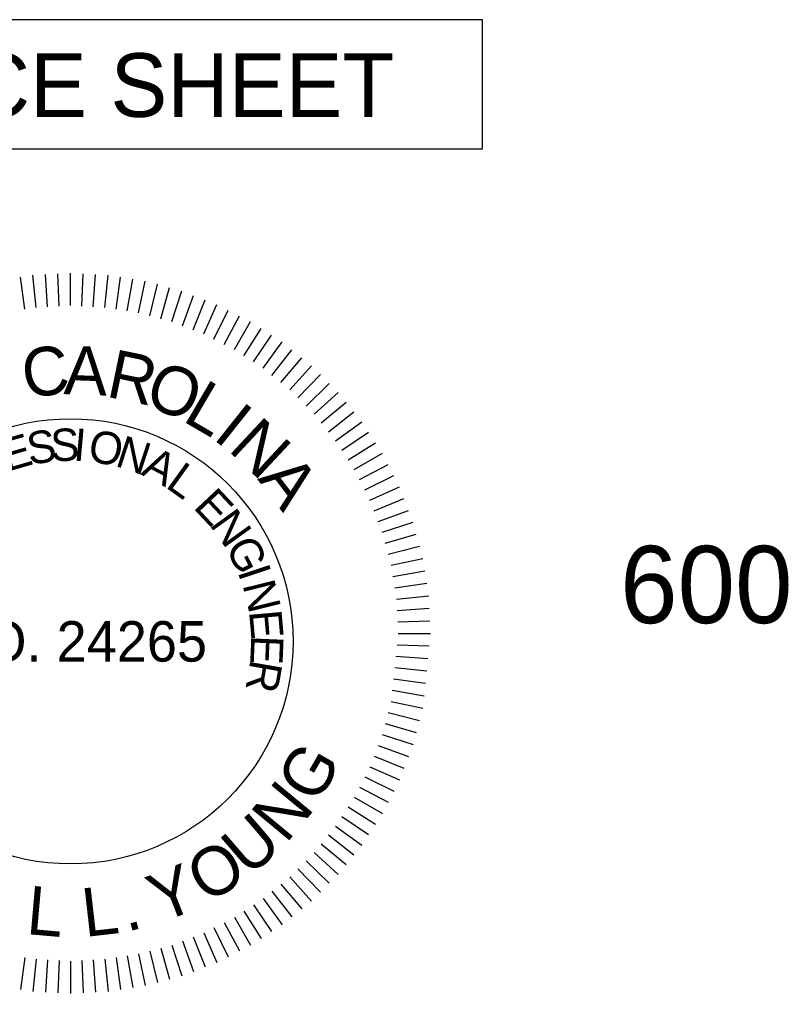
# Model space of a CAD drawing. Extents: x 1964377 to 1966966, y 1116414 to 1123213.
# Drawn here: x 1966865.3 to 1966949.9, y 1120286.1 to 1120393.2 of the extents above; entities that cross this region are included whole.
import ezdxf

# ---------------------------------------------------------------- set-up
doc = ezdxf.new("R2010")
doc.units = 0
for name, color, linetype in [('RD_DDB_Profile_Elev', 7, 'Continuous'), ('RD_Sketch1', 7, 'Continuous'), ('RD_TX_PEShield', 7, 'Continuous')]:
    doc.layers.add(name, color=color, linetype=linetype)

msp = doc.modelspace()

# ---------------------------------------------------------------- linework, layer by layer
at = {"layer": 'RD_Sketch1'}
msp.add_lwpolyline([(1966615.77, 1120393.19), (1966916.19, 1120393.19), (1966916.19, 1120378.93), (1966615.77, 1120378.93)], close=True, dxfattribs=at)
at = {"layer": 'RD_TX_PEShield'}
for p, q in [((1966868.39, 1120361.59), (1966868.14, 1120365.14)), ((1966868.39, 1120361.59), (1966868.14, 1120365.14)), ((1966869.64, 1120361.65), (1966869.52, 1120365.21)), ((1966869.64, 1120361.65), (1966869.52, 1120365.21)), ((1966870.9, 1120361.72), (1966870.9, 1120365.28)), ((1966870.9, 1120361.72), (1966870.9, 1120365.28)), ((1966872.15, 1120361.65), (1966872.28, 1120365.21)), ((1966872.15, 1120361.65), (1966872.28, 1120365.21)), ((1966873.41, 1120361.59), (1966873.66, 1120365.14)), ((1966873.41, 1120361.59), (1966873.66, 1120365.14)), ((1966865.89, 1120361.33), (1966865.39, 1120364.85)), ((1966865.89, 1120361.33), (1966865.39, 1120364.85)), ((1966867.13, 1120361.52), (1966866.76, 1120365.06)), ((1966867.13, 1120361.52), (1966866.76, 1120365.06)), ((1966874.67, 1120361.52), (1966875.04, 1120365.06)), ((1966874.67, 1120361.52), (1966875.04, 1120365.06)), ((1966875.91, 1120361.33), (1966876.4, 1120364.85)), ((1966875.91, 1120361.33), (1966876.4, 1120364.85)), ((1966877.15, 1120361.13), (1966877.77, 1120364.63)), ((1966877.15, 1120361.13), (1966877.77, 1120364.63)), ((1966878.39, 1120360.93), (1966879.13, 1120364.41)), ((1966878.39, 1120360.93), (1966879.13, 1120364.41)), ((1966878.39, 1120360.93), (1966879.13, 1120364.41)), ((1966879.61, 1120360.61), (1966880.47, 1120364.06)), ((1966879.61, 1120360.61), (1966880.47, 1120364.06)), ((1966879.61, 1120360.61), (1966880.47, 1120364.06)), ((1966880.82, 1120360.28), (1966881.8, 1120363.7)), ((1966880.82, 1120360.28), (1966881.8, 1120363.7)), ((1966880.82, 1120360.28), (1966881.8, 1120363.7)), ((1966882.04, 1120359.96), (1966883.14, 1120363.34)), ((1966882.04, 1120359.96), (1966883.14, 1120363.34)), ((1966882.04, 1120359.96), (1966883.14, 1120363.34)), ((1966883.21, 1120359.51), (1966884.43, 1120362.85)), ((1966883.21, 1120359.51), (1966884.43, 1120362.85)), ((1966883.21, 1120359.51), (1966884.43, 1120362.85)), ((1966884.38, 1120359.06), (1966885.72, 1120362.35)), ((1966884.38, 1120359.06), (1966885.72, 1120362.35)), ((1966884.38, 1120359.06), (1966885.72, 1120362.35)), ((1966885.56, 1120358.6), (1966887.01, 1120361.86)), ((1966885.56, 1120358.6), (1966887.01, 1120361.86)), ((1966885.56, 1120358.6), (1966887.01, 1120361.86)), ((1966886.68, 1120358.03), (1966888.24, 1120361.23)), ((1966886.68, 1120358.03), (1966888.24, 1120361.23)), ((1966886.68, 1120358.03), (1966888.24, 1120361.23)), ((1966887.8, 1120357.46), (1966889.47, 1120360.6)), ((1966887.8, 1120357.46), (1966889.47, 1120360.6)), ((1966887.8, 1120357.46), (1966889.47, 1120360.6)), ((1966888.92, 1120356.89), (1966890.7, 1120359.97)), ((1966888.92, 1120356.89), (1966890.7, 1120359.97)), ((1966888.92, 1120356.89), (1966890.7, 1120359.97)), ((1966889.98, 1120356.21), (1966891.86, 1120359.22)), ((1966889.98, 1120356.21), (1966891.86, 1120359.22)), ((1966889.98, 1120356.21), (1966891.86, 1120359.22)), ((1966891.03, 1120355.52), (1966893.02, 1120358.47)), ((1966891.03, 1120355.52), (1966893.02, 1120358.47)), ((1966891.03, 1120355.52), (1966893.02, 1120358.47)), ((1966892.09, 1120354.84), (1966894.18, 1120357.72)), ((1966892.09, 1120354.84), (1966894.18, 1120357.72)), ((1966892.09, 1120354.84), (1966894.18, 1120357.72)), ((1966893.06, 1120354.04), (1966895.25, 1120356.85)), ((1966893.06, 1120354.04), (1966895.25, 1120356.85)), ((1966893.06, 1120354.04), (1966895.25, 1120356.85)), ((1966894.04, 1120353.25), (1966896.33, 1120355.98)), ((1966894.04, 1120353.25), (1966896.33, 1120355.98)), ((1966894.04, 1120353.25), (1966896.33, 1120355.98)), ((1966895.02, 1120352.46), (1966897.4, 1120355.11)), ((1966895.02, 1120352.46), (1966897.4, 1120355.11)), ((1966895.02, 1120352.46), (1966897.4, 1120355.11)), ((1966895.91, 1120351.57), (1966898.38, 1120354.13)), ((1966895.91, 1120351.57), (1966898.38, 1120354.13)), ((1966895.91, 1120351.57), (1966898.38, 1120354.13)), ((1966896.8, 1120350.68), (1966899.35, 1120353.15)), ((1966896.8, 1120350.68), (1966899.35, 1120353.15)), ((1966896.8, 1120350.68), (1966899.35, 1120353.15)), ((1966897.69, 1120349.79), (1966900.33, 1120352.18)), ((1966897.69, 1120349.79), (1966900.33, 1120352.18)), ((1966897.69, 1120349.79), (1966900.33, 1120352.18)), ((1966898.48, 1120348.82), (1966901.2, 1120351.1)), ((1966898.48, 1120348.82), (1966901.2, 1120351.1)), ((1966898.48, 1120348.82), (1966901.2, 1120351.1)), ((1966899.27, 1120347.84), (1966902.07, 1120350.03)), ((1966899.27, 1120347.84), (1966902.07, 1120350.03)), ((1966899.27, 1120347.84), (1966902.07, 1120350.03)), ((1966900.06, 1120346.86), (1966902.94, 1120348.95)), ((1966900.06, 1120346.86), (1966902.94, 1120348.95)), ((1966900.06, 1120346.86), (1966902.94, 1120348.95)), ((1966900.74, 1120345.81), (1966903.69, 1120347.8)), ((1966900.74, 1120345.81), (1966903.69, 1120347.8)), ((1966900.74, 1120345.81), (1966903.69, 1120347.8)), ((1966901.43, 1120344.75), (1966904.44, 1120346.64)), ((1966901.43, 1120344.75), (1966904.44, 1120346.64)), ((1966901.43, 1120344.75), (1966904.44, 1120346.64)), ((1966902.11, 1120343.7), (1966905.2, 1120345.48)), ((1966902.11, 1120343.7), (1966905.2, 1120345.48)), ((1966902.11, 1120343.7), (1966905.2, 1120345.48)), ((1966902.69, 1120342.58), (1966905.83, 1120344.25)), ((1966902.69, 1120342.58), (1966905.83, 1120344.25)), ((1966902.69, 1120342.58), (1966905.83, 1120344.25)), ((1966903.26, 1120341.46), (1966906.45, 1120343.02)), ((1966903.26, 1120341.46), (1966906.45, 1120343.02)), ((1966903.26, 1120341.46), (1966906.45, 1120343.02)), ((1966903.83, 1120340.34), (1966907.08, 1120341.78)), ((1966903.83, 1120340.34), (1966907.08, 1120341.78)), ((1966903.83, 1120340.34), (1966907.08, 1120341.78)), ((1966904.28, 1120339.16), (1966907.57, 1120340.49)), ((1966904.28, 1120339.16), (1966907.57, 1120340.49)), ((1966904.28, 1120339.16), (1966907.57, 1120340.49)), ((1966904.73, 1120337.99), (1966908.07, 1120339.2)), ((1966904.73, 1120337.99), (1966908.07, 1120339.2)), ((1966904.73, 1120337.99), (1966908.07, 1120339.2)), ((1966905.18, 1120336.81), (1966908.57, 1120337.91)), ((1966905.18, 1120336.81), (1966908.57, 1120337.91)), ((1966905.18, 1120336.81), (1966908.57, 1120337.91)), ((1966905.5, 1120335.6), (1966908.92, 1120336.58)), ((1966905.5, 1120335.6), (1966908.92, 1120336.58)), ((1966905.5, 1120335.6), (1966908.92, 1120336.58)), ((1966905.83, 1120334.38), (1966909.28, 1120335.25)), ((1966905.83, 1120334.38), (1966909.28, 1120335.25)), ((1966905.83, 1120334.38), (1966909.28, 1120335.25)), ((1966906.16, 1120333.17), (1966909.64, 1120333.91)), ((1966906.16, 1120333.17), (1966909.64, 1120333.91)), ((1966906.16, 1120333.17), (1966909.64, 1120333.91)), ((1966906.35, 1120331.93), (1966909.85, 1120332.54)), ((1966906.35, 1120331.93), (1966909.85, 1120332.54)), ((1966906.35, 1120331.93), (1966909.85, 1120332.54)), ((1966906.55, 1120330.69), (1966910.07, 1120331.18)), ((1966906.55, 1120330.69), (1966910.07, 1120331.18)), ((1966906.55, 1120330.69), (1966910.07, 1120331.18)), ((1966906.75, 1120329.44), (1966910.29, 1120329.82)), ((1966906.75, 1120329.44), (1966910.29, 1120329.82)), ((1966906.75, 1120329.44), (1966910.29, 1120329.82)), ((1966906.81, 1120328.19), (1966910.36, 1120328.43)), ((1966906.81, 1120328.19), (1966910.36, 1120328.43)), ((1966906.81, 1120328.19), (1966910.36, 1120328.43)), ((1966906.88, 1120326.93), (1966910.43, 1120327.06)), ((1966906.88, 1120326.93), (1966910.43, 1120327.06)), ((1966906.88, 1120326.93), (1966910.43, 1120327.06)), ((1966906.94, 1120325.68), (1966910.5, 1120325.68)), ((1966906.94, 1120325.68), (1966910.5, 1120325.68)), ((1966906.94, 1120325.68), (1966910.5, 1120325.68)), ((1966906.81, 1120324.42), (1966910.36, 1120324.3)), ((1966906.81, 1120324.42), (1966910.36, 1120324.3)), ((1966906.68, 1120323.17), (1966910.21, 1120322.93)), ((1966906.68, 1120323.17), (1966910.21, 1120322.93)), ((1966906.55, 1120321.93), (1966910.07, 1120321.56)), ((1966906.55, 1120321.93), (1966910.07, 1120321.56)), ((1966906.42, 1120320.68), (1966909.93, 1120320.19)), ((1966906.42, 1120320.68), (1966909.93, 1120320.19)), ((1966906.29, 1120319.44), (1966909.78, 1120318.82)), ((1966906.29, 1120319.44), (1966909.78, 1120318.82)), ((1966906.16, 1120318.18), (1966909.64, 1120317.44)), ((1966906.16, 1120318.18), (1966909.64, 1120317.44)), ((1966905.83, 1120316.97), (1966909.28, 1120316.11)), ((1966905.83, 1120316.97), (1966909.28, 1120316.11)), ((1966905.5, 1120315.75), (1966908.92, 1120314.77)), ((1966905.5, 1120315.75), (1966908.92, 1120314.77)), ((1966905.18, 1120314.54), (1966908.57, 1120313.44)), ((1966905.18, 1120314.54), (1966908.57, 1120313.44)), ((1966904.73, 1120313.36), (1966908.07, 1120312.15)), ((1966904.73, 1120313.36), (1966908.07, 1120312.15)), ((1966904.28, 1120312.19), (1966907.57, 1120310.86)), ((1966904.28, 1120312.19), (1966907.57, 1120310.86)), ((1966903.83, 1120311.01), (1966907.08, 1120309.57)), ((1966903.83, 1120311.01), (1966907.08, 1120309.57)), ((1966903.26, 1120309.89), (1966906.45, 1120308.33)), ((1966903.26, 1120309.89), (1966906.45, 1120308.33)), ((1966902.69, 1120308.77), (1966905.83, 1120307.1)), ((1966902.69, 1120308.77), (1966905.83, 1120307.1)), ((1966902.11, 1120307.65), (1966905.2, 1120305.87)), ((1966902.11, 1120307.65), (1966905.2, 1120305.87)), ((1966901.43, 1120306.6), (1966904.44, 1120304.71)), ((1966901.43, 1120306.6), (1966904.44, 1120304.71)), ((1966900.74, 1120305.54), (1966903.69, 1120303.56)), ((1966900.74, 1120305.54), (1966903.69, 1120303.56)), ((1966900.06, 1120304.49), (1966902.94, 1120302.4)), ((1966900.06, 1120304.49), (1966902.94, 1120302.4)), ((1966899.27, 1120303.51), (1966902.07, 1120301.32)), ((1966899.27, 1120303.51), (1966902.07, 1120301.32)), ((1966898.48, 1120302.53), (1966901.2, 1120300.25)), ((1966898.48, 1120302.53), (1966901.2, 1120300.25)), ((1966897.69, 1120301.56), (1966900.33, 1120299.17)), ((1966897.69, 1120301.56), (1966900.33, 1120299.17)), ((1966895.91, 1120299.78), (1966898.38, 1120297.22)), ((1966895.91, 1120299.78), (1966898.38, 1120297.22)), ((1966896.8, 1120300.67), (1966899.35, 1120298.2)), ((1966896.8, 1120300.67), (1966899.35, 1120298.2)), ((1966895.02, 1120298.89), (1966897.4, 1120296.24)), ((1966894.04, 1120298.1), (1966896.33, 1120295.37)), ((1966894.04, 1120298.1), (1966896.33, 1120295.37)), ((1966892.09, 1120296.51), (1966894.18, 1120293.63)), ((1966892.09, 1120296.51), (1966894.18, 1120293.63)), ((1966893.06, 1120297.31), (1966895.25, 1120294.5)), ((1966893.06, 1120297.31), (1966895.25, 1120294.5)), ((1966891.03, 1120295.83), (1966893.02, 1120292.88)), ((1966891.03, 1120295.83), (1966893.02, 1120292.88)), ((1966888.92, 1120294.46), (1966890.7, 1120291.38)), ((1966888.92, 1120294.46), (1966890.7, 1120291.38)), ((1966889.98, 1120295.14), (1966891.86, 1120292.13)), ((1966889.98, 1120295.14), (1966891.86, 1120292.13)), ((1966886.68, 1120293.32), (1966888.24, 1120290.12)), ((1966886.68, 1120293.32), (1966888.24, 1120290.12)), ((1966887.8, 1120293.89), (1966889.47, 1120290.75)), ((1966887.8, 1120293.89), (1966889.47, 1120290.75)), ((1966884.38, 1120292.3), (1966885.72, 1120289)), ((1966884.38, 1120292.3), (1966885.72, 1120289)), ((1966885.56, 1120292.75), (1966887.01, 1120289.49)), ((1966885.56, 1120292.75), (1966887.01, 1120289.49)), ((1966882.04, 1120291.39), (1966883.14, 1120288.01)), ((1966882.04, 1120291.39), (1966883.14, 1120288.01)), ((1966883.21, 1120291.85), (1966884.43, 1120288.5)), ((1966883.21, 1120291.85), (1966884.43, 1120288.5)), ((1966877.15, 1120290.22), (1966877.77, 1120286.72)), ((1966877.15, 1120290.22), (1966877.77, 1120286.72)), ((1966878.39, 1120290.42), (1966879.13, 1120286.94)), ((1966878.39, 1120290.42), (1966879.13, 1120286.94)), ((1966879.61, 1120290.74), (1966880.47, 1120287.29)), ((1966879.61, 1120290.74), (1966880.47, 1120287.29)), ((1966880.82, 1120291.07), (1966881.8, 1120287.65)), ((1966880.82, 1120291.07), (1966881.8, 1120287.65)), ((1966865.89, 1120290.02), (1966865.39, 1120286.5)), ((1966865.89, 1120290.02), (1966865.39, 1120286.5)), ((1966867.13, 1120289.83), (1966866.76, 1120286.29)), ((1966867.13, 1120289.83), (1966866.76, 1120286.29)), ((1966868.39, 1120289.76), (1966868.14, 1120286.21)), ((1966868.39, 1120289.76), (1966868.14, 1120286.21)), ((1966869.64, 1120289.7), (1966869.52, 1120286.14)), ((1966869.64, 1120289.7), (1966869.52, 1120286.14)), ((1966870.9, 1120289.63), (1966870.9, 1120286.07)), ((1966870.9, 1120289.63), (1966870.9, 1120286.07)), ((1966872.15, 1120289.7), (1966872.28, 1120286.14)), ((1966872.15, 1120289.7), (1966872.28, 1120286.14)), ((1966873.41, 1120289.76), (1966873.66, 1120286.21)), ((1966873.41, 1120289.76), (1966873.66, 1120286.21)), ((1966874.67, 1120289.83), (1966875.04, 1120286.29)), ((1966874.67, 1120289.83), (1966875.04, 1120286.29)), ((1966875.91, 1120290.02), (1966876.4, 1120286.5)), ((1966875.91, 1120290.02), (1966876.4, 1120286.5))]:
    msp.add_line(p, q, dxfattribs=at)
msp.add_circle((1966870.9, 1120324.8), 24.48, dxfattribs=at)

# ---------------------------------------------------------------- texts
at = {"layer": 'RD_DDB_Profile_Elev'}
msp.add_text('600', height=8.5, dxfattribs=at).set_placement((1966931.34, 1120326.8))
at = {"layer": 'RD_Sketch1'}
msp.add_text('ALIGNMENT CONTROL CAN BE FOUND ON REFERENCE SHEET', height=7, dxfattribs=at).set_placement((1966619.42, 1120382.47))
at = {"layer": 'RD_TX_PEShield'}
for s, height, rotation, p in [('C', 5.34, 6.8832, (1966865.89, 1120351.54)), ('A', 5.34, 357.9448, (1966870.11, 1120351.99)), ('R', 5.34, 348.267, (1966874.69, 1120351.73)), ('O', 5.34, 339.3286, (1966878.83, 1120350.82)), ('L', 5.34, 329.6507, (1966883.09, 1120349.11)), ('I', 5.34, 321.4663, (1966886.43, 1120347.13)), ('N', 5.34, 317.0007, (1966888.12, 1120345.85)), ('S', 3.56, 8.6909, (1966866.39, 1120344.19)), ('S', 3.56, 1.79, (1966868.75, 1120344.59)), ('I', 3.56, 354.889, (1966871.14, 1120344.7)), ('O', 3.56, 350.4045, (1966872.7, 1120344.62)), ('E', 3.56, 16.1843, (1966863.9, 1120343.43)), ('N', 3.56, 341.7029, (1966875.68, 1120344.12)), ('A', 3.56, 333.0013, (1966878.54, 1120343.18)), ('L', 3.56, 324.2997, (1966881.24, 1120341.81)), ('A', 5.34, 307.3229, (1966891.41, 1120342.66)), ('E', 3.56, 313.2251, (1966884.31, 1120339.51)), ('N', 3.56, 305.7317, (1966886.12, 1120337.63)), ('G', 3.56, 297.0301, (1966887.88, 1120335.18)), ('I', 3.56, 288.3285, (1966889.26, 1120332.49)), ('N', 3.56, 283.8441, (1966889.8, 1120331.03)), ('E', 3.56, 275.1424, (1966890.53, 1120328.1)), ('E', 3.56, 267.6491, (1966890.79, 1120325.51)), ('R', 3.56, 260.1557, (1966890.72, 1120322.91)), ('G', 5.34, 60.1113, (1966898.01, 1120306.77)), ('N', 5.34, 50.4335, (1966894.59, 1120302.47)), ('U', 5.34, 40.7556, (1966890.5, 1120298.81)), ('O', 5.34, 31.0778, (1966885.85, 1120295.88)), ('Y', 5.34, 21.4, (1966880.78, 1120293.78)), ('L', 5.34, 354.9835, (1966865.95, 1120292.62)), ('L', 5.34, 6.5171, (1966872.48, 1120292.28)), ('.', 5.34, 14.7016, (1966877.09, 1120292.84))]:
    msp.add_text(s, height=height, rotation=rotation, dxfattribs=at).set_placement(p)
msp.add_text('NO. 24265', height=4.45, dxfattribs=at).set_placement((1966857.14, 1120322.57))

doc.saveas('drawing.dxf')
